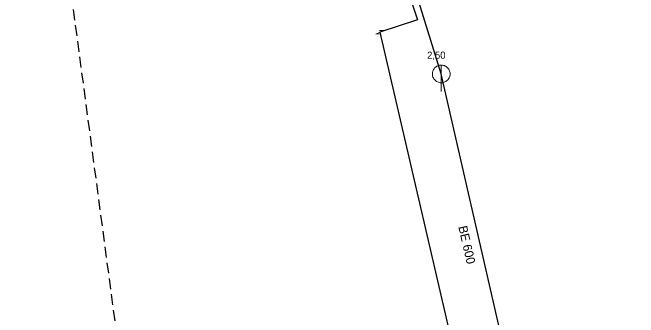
# Model space of a CAD drawing. Extents: x -682839 to -682312, y -994645 to -993949.
# Drawn here: x -682751.4 to -682680.8, y -994128.9 to -994094.5 of the extents above; entities that cross this region are included whole.
import ezdxf

# ---------------------------------------------------------------- set-up
doc = ezdxf.new("R2010")
doc.units = 0
doc.header["$LTSCALE"] = 0.4
doc.linetypes.add('MEDIUM_DASHED', pattern=[4.5, 3, -1.5])
doc.layers.add('1', color=7, linetype='Continuous')
for name, color, linetype, lineweight in [('14', 7, 'Continuous', 25), ('17', 7, 'Continuous', 25), ('22', 7, 'Continuous', 13), ('47', 7, 'Continuous', 13), ('63', 7, 'MEDIUM_DASHED', 25)]:
    doc.layers.add(name, color=color, linetype=linetype, lineweight=lineweight)

msp = doc.modelspace()

# ---------------------------------------------------------------- linework, layer by layer
at = {"layer": '14'}
for p, q in [((-682703.07, -994101.399), (-682709.039, -994082.17)), ((-682694.03, -994140.85), (-682703.07, -994101.399))]:
    msp.add_line(p, q, dxfattribs=at)
at = {"layer": '17'}
for points in [[(-682709.519, -994079.82), (-682709.48, -994080.039), (-682710.079, -994082.26), (-682705.76, -994095.289), (-682710, -994096.699)], [(-682710, -994096.699), (-682700.333, -994138.327), (-682682.065, -994177.804)]]:
    msp.add_lwpolyline(points, dxfattribs=at)
at = {"layer": '22'}
msp.add_line((-682703.07, -994103.399), (-682703.069, -994100.399), dxfattribs=at)
msp.add_lwpolyline([(-682702.07, -994101.399), (-682702.075, -994101.29), (-682702.093, -994101.182), (-682702.123, -994101.076), (-682702.163, -994100.975), (-682702.215, -994100.878), (-682702.277, -994100.788), (-682702.349, -994100.705), (-682702.429, -994100.631), (-682702.517, -994100.565), (-682702.611, -994100.51), (-682702.711, -994100.465), (-682702.816, -994100.432), (-682702.923, -994100.41), (-682703.032, -994100.4), (-682703.142, -994100.402), (-682703.25, -994100.416), (-682703.357, -994100.441), (-682703.46, -994100.478), (-682703.558, -994100.527), (-682703.65, -994100.585), (-682703.736, -994100.654), (-682703.813, -994100.731), (-682703.882, -994100.817), (-682703.941, -994100.909), (-682703.989, -994101.007), (-682704.026, -994101.11), (-682704.052, -994101.217), (-682704.066, -994101.325), (-682704.069, -994101.435), (-682704.059, -994101.544), (-682704.038, -994101.651), (-682704.004, -994101.755), (-682703.96, -994101.855), (-682703.905, -994101.95), (-682703.839, -994102.038), (-682703.765, -994102.118), (-682703.682, -994102.19), (-682703.592, -994102.252), (-682703.496, -994102.304), (-682703.394, -994102.345), (-682703.289, -994102.375), (-682703.181, -994102.393), (-682703.071, -994102.399), (-682702.962, -994102.393), (-682702.854, -994102.375), (-682702.749, -994102.346), (-682702.647, -994102.305), (-682702.55, -994102.253), (-682702.46, -994102.191), (-682702.377, -994102.12), (-682702.302, -994102.04), (-682702.237, -994101.952), (-682702.181, -994101.858), (-682702.137, -994101.758), (-682702.103, -994101.654), (-682702.081, -994101.546), (-682702.071, -994101.437)], close=True, dxfattribs=at)
at = {"layer": '47'}
msp.add_line((-682709.535, -994096.49), (-682710.045, -994096.503), dxfattribs=at)
msp.add_lwpolyline([(-682709.535, -994096.49), (-682710.464, -994096.907), (-682709.954, -994096.894)], dxfattribs=at)
at = {"layer": '63'}
msp.add_lwpolyline([(-682494.62, -994477.955), (-682564.4, -994570.065), (-682564.4, -994570.065), (-682684.423, -994544.944), (-682684.423, -994544.944), (-682751.412, -994042.525), (-682751.412, -994042.525), (-682670.466, -994042.525), (-682670.466, -994042.525)], close=True, dxfattribs=at)

# ---------------------------------------------------------------- texts
at = {"layer": '1'}
msp.add_text('2,50', height=0.8, dxfattribs=at).set_placement((-682704.67, -994099.688))
msp.add_text('BE 600', height=1, rotation=283, dxfattribs=at).set_placement((-682701.154, -994118.643))

doc.saveas('drawing.dxf')
